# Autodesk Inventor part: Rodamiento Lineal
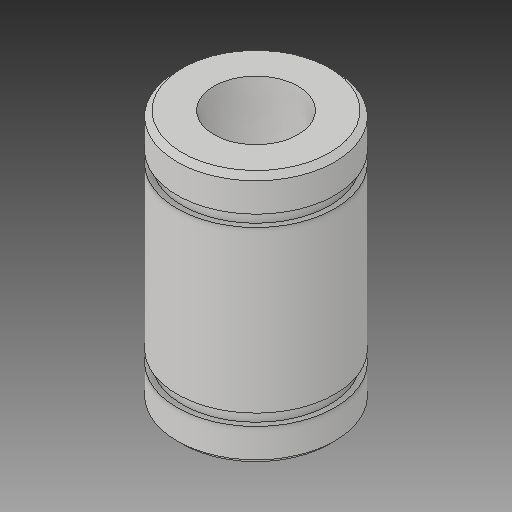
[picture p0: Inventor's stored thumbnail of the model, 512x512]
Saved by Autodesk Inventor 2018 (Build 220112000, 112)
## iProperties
Part Number: Rodamiento Lineal
Material: Genérico
Document SubType Name: Modeling
Designer: ULISES
Density: 1 g/cm^3
Appearance: Valor por defecto
Mass: 2.97315 g
Surface Area: 20.43 cm^2
Volume: 2.97315 cm^3
Author: ULISES
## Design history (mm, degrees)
sketch "Boceto2"
  geometry: L1 (0, 0)-(0, 24); L2 (4, 0)-(7.5, 0); L3 (7.5, 24)-(4, 24); L4 (4, 24)-(4, 0); L5 (7.5, 4.35)-(7, 4.35); L6 (7, 4.35)-(7, 3.25); L7 (7, 3.25)-(7.5, 3.25); L8 (7.5, 20.75)-(7, 20.75); L9 (7, 20.75)-(7, 19.65); L10 (7, 19.65)-(7.5, 19.65); L11 (7.5, 0)-(7.5, 3.25); L12 (7.5, 4.35)-(7.5, 19.65); L13 (7.5, 20.75)-(7.5, 24); 1 further point
  constraints: 26 end point, 6 parallel, 5 perpendicular, 3 horizontal, 2 collinear, 1 horizontal alignment, 1 midpoint, 1 vertical
  dimensions: "d5" = 24 distance of L1.start L1.end; "d6" = 4 distance between parallel lines of L1 L4; "d7" = 24 distance of L2.end L3.start; "d9" = 3.25 distance between parallel lines of L8 L3; "d10" = 1.1 distance of L8.end L9.end; "d12" = 3.25 distance between parallel lines of L2 L7; "d14" = 1.1 distance of L5.end L6.end; "d15" = 3.5 distance between parallel lines of L4 L11; "d16" = 0.5 distance between parallel lines of L13 L9; "d17" = 0.5 distance between parallel lines of L12 L6; "d22" = 7.5 distance between parallel lines of L1 L13 (derived)
revolve "Revolución1" sketch "Boceto2" stored, may be unused: angle "d18" = 90 deg
chamfer "Chaflán1" distance "d19" = 0.5; stored, may be unused: second distance "d20" = 2, angle "d21" = 45 deg
node "Sólido2"
other parameters: "d8" = 3.5, "d11" = 0.5, "d13" = 0.5
